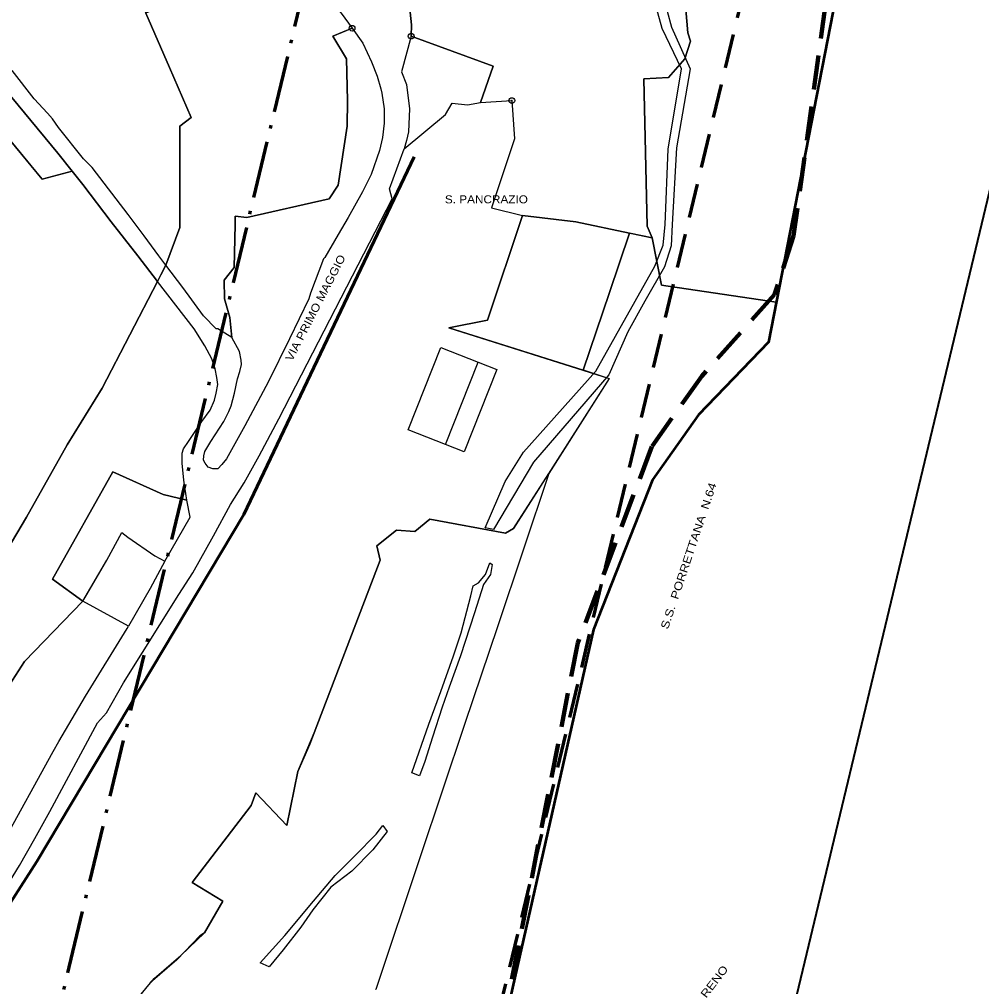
# Model space of a CAD drawing. Extents: x 654952 to 658955, y 890426 to 894481.
# Drawn here: x 657975.8 to 658312.8, y 892673.6 to 893012.3 of the extents above; entities that cross this region are included whole.
import ezdxf

# ---------------------------------------------------------------- set-up
doc = ezdxf.new("R2010")
doc.units = 0
doc.header["$LTSCALE"] = 4
doc.header["$PDMODE"] = 32
doc.header["$PDSIZE"] = 2
doc.linetypes.add('DOT_DASHED', pattern=[7.7, 5, -1.2, 0.3, -1.2])
doc.linetypes.add('MEDIUM_DASHED', pattern=[4.5, 3, -1.5])
for name, color, linetype, lineweight in [('1', 7, 'Continuous', 25), ('14', 7, 'Continuous', 25), ('18', 7, 'Continuous', 25), ('20', 7, 'Continuous', 25), ('29', 7, 'Continuous', 25), ('40', 7, 'Continuous', 60), ('43', 7, 'Continuous', 25), ('45', 7, 'Continuous', 25), ('5', 7, 'Continuous', 25), ('55', 7, 'Continuous', 25), ('57', 7, 'Continuous', 25), ('59', 7, 'Continuous', 53), ('6', 7, 'Continuous', 25), ('7', 7, 'MEDIUM_DASHED', 100), ('9', 7, 'Continuous', 25)]:
    doc.layers.add(name, color=color, linetype=linetype, lineweight=lineweight)
doc.layers.add('58', color=7, linetype='Continuous')

msp = doc.modelspace()

# ---------------------------------------------------------------- linework, layer by layer
at = {"layer": '1'}
for points in [[(657998.02, 892808.54), (657999.47, 892810.89), (658006.47, 892822.89), (658011.7, 892832.58), (658013.75, 892830.94), (658023.25, 892824.44)], [(658023.25, 892824.44), (658026.8, 892822.52), (658021.63, 892812.94), (658013.98, 892799.82), (657998.08, 892808.51)]]:
    msp.add_lwpolyline(points, dxfattribs=at)
at = {"layer": '14'}
for points in [[(658077.75, 892916.44), (658077.13, 892914.44), (658070.37, 892900.44), (658063, 892885.44), (658054.75, 892869.94), (658048.37, 892858.44), (658046.75, 892856.44), (658045.25, 892854.94), (658043.5, 892854.94), (658041.87, 892855.44), (658040.87, 892856.94), (658040.25, 892857.94), (658040.37, 892859.44), (658040.75, 892860.94), (658042.87, 892864.44), (658047.38, 892871.44), (658049.13, 892874.94), (658050, 892876.94), (658051.13, 892881.44), (658052.25, 892886.44), (658053, 892888.94), (658053.63, 892891.44), (658053.5, 892892.94), (658052.87, 892895.94), (658050.25, 892900.94), (658049.5, 892907.94), (658047.63, 892914.44), (658047.5, 892920.94), (658051.06, 892925.44), (658051.37, 892940.44), (658051.37, 892943.44), (658055.5, 892942.94), (658084.25, 892949.44), (658087.44, 892954.19), (658090.63, 892974.94), (658090.75, 892983.94), (658090.31, 892998.44), (658085.63, 893006.44), (658092.31, 893009.19)], [(658092.31, 893009.19), (658092.31, 893009.19), (658096.13, 893003.94), (658099.13, 892997.44), (658101.13, 892992.44), (658102.37, 892987.94), (658102.75, 892986.44)], [(658102.75, 892986.44), (658103.5, 892980.94), (658103.5, 892975.94), (658103, 892970.94), (658101.87, 892966.44), (658099, 892957.94), (658096, 892951.94), (658091, 892942.94), (658087.5, 892936.94), (658082.75, 892928.94), (658082.25, 892928.44), (658077.75, 892916.44)]]:
    msp.add_lwpolyline(points, dxfattribs=at)
msp.add_point((658092.31, 893009.19), dxfattribs=at)
at = {"layer": '18'}
for points in [[(657994.29, 892959.11), (657989.25, 892965.44), (657968.05, 892991.04), (657966.89, 892992.59), (657957.1, 892988.98), (657960.05, 892985.04), (657960.35, 892984.66)], [(657960.35, 892984.66), (657981.49, 892959.14), (657983.75, 892956.29), (657994.29, 892959.11)]]:
    msp.add_lwpolyline(points, dxfattribs=at)
at = {"layer": '20'}
msp.add_line((658026.13, 892845.94), (658034.45, 892843.92), dxfattribs=at)
for points in [[(658024.17, 892920.51), (658017.25, 892929.44), (658008, 892941.44), (657998, 892954.44), (657994.29, 892959.11), (657983.75, 892956.29), (657967.25, 892976.32), (657932.13, 892896.94), (657930.01, 892892.15), (657906.64, 892839.36), (657926, 892830.44), (657930.13, 892846.94), (657960.5, 892838.94), (657961.09, 892814.26), (657961.21, 892809.33)], [(658024.17, 892920.51), (658004.83, 892883.1), (657992.56, 892863.36), (657978.36, 892837.99), (657961.21, 892809.33), (657961.5, 892797.44), (657962.87, 892782.94), (657962.48, 892768.22), (657964.75, 892767.48), (657969.21, 892774.37), (657977.66, 892787.42), (657998.02, 892808.54)], [(657961.21, 892809.33), (657978.36, 892837.99), (657992.56, 892863.36), (658004.83, 892883.1), (658024.17, 892920.51)], [(658034.45, 892843.92), (658033.37, 892850.94), (658032.87, 892856.94), (658032.87, 892860.44), (658033.25, 892861.94), (658035, 892864.44), (658039.75, 892871.44), (658042.63, 892875.44), (658044.13, 892878.94), (658044.75, 892881.44), (658045.25, 892884.44), (658045, 892886.94), (658044.37, 892889.94), (658043.25, 892893.44), (658040.75, 892897.94), (658037, 892903.94), (658024.17, 892920.51)], [(657998.02, 892808.54), (657987.36, 892816.2), (658008.58, 892853.84), (658026.13, 892845.94)]]:
    msp.add_lwpolyline(points, dxfattribs=at)
at = {"layer": '29'}
for points in [[(658222.69, 893076.77), (658218.01, 893077.46), (658207.53, 893075.52), (658196.6, 893076.12), (658185.51, 893078.96), (658169.41, 893074.9), (658169.53, 893074.45), (658153.5, 893069.94), (658152, 893062.44), (658144.5, 893060.94), (658133.63, 893069.44), (658129.75, 893066.44), (658108.5, 893069.94), (658106.87, 893067.94), (658106.75, 893058.44), (658107.75, 893046.94), (658109.25, 893046.94), (658113.13, 893010.44), (658113, 893006.44)], [(658203.13, 892991.94), (658208.87, 892998.44), (658210.87, 893004.69), (658209.9, 893007.55), (658208.52, 893024.05), (658215.39, 893024.69), (658218.4, 893043.42), (658221.75, 893066.94), (658222.69, 893076.77)], [(658113, 893006.44), (658141.75, 892995.94), (658137.25, 892983.17), (658148.26, 892983.85)], [(658195.63, 892939.94), (658194.44, 892991.44), (658203.13, 892991.94)], [(658106.37, 892949.44), (658105.37, 892952.94), (658110.5, 892966.94), (658125, 892978.94), (658127.37, 892982.94), (658132.74, 892982.34), (658137.25, 892983.17), (658148.26, 892983.85), (658149.18, 892970.5), (658141.15, 892946.27), (658151.94, 892943.62)], [(658148.26, 892983.85), (658149.18, 892970.5), (658141.15, 892946.27), (658151.94, 892943.62), (658170.62, 892941.41)], [(657975.87, 892715.94), (657981.19, 892725.44), (657986.5, 892734.94), (658003.13, 892765.94), (658006.37, 892769.44), (658012.25, 892779.94), (658031.63, 892810.94), (658036.5, 892818.44), (658043.75, 892831.44), (658049.75, 892842.44), (658054.5, 892849.94), (658059.81, 892859.44), (658066.63, 892872.44), (658106.37, 892949.44)], [(658151.94, 892943.62), (658139.73, 892906.94), (658126.18, 892904.28)], [(658170.62, 892941.41), (658197.42, 892935.77), (658195.63, 892939.94)], [(658126.18, 892904.28), (658182.31, 892886.53), (658148.87, 892834.03), (658146, 892832.35), (658119.5, 892837.28), (658114.24, 892832.91), (658107.87, 892833.47), (658101, 892827.94), (658102.13, 892822.94), (658077.5, 892758.44), (658073.37, 892748.94), (658069.5, 892729.94), (658058.63, 892741.44), (658057, 892736.94), (658036.31, 892709.98), (658047, 892703.44), (658040.63, 892692.44), (658038.98, 892691.29)], [(657956, 892639.44), (657953.37, 892639.94), (657950.75, 892640.94), (657948.5, 892641.94), (657945.87, 892644.44), (657937.08, 892655.43), (657938.63, 892657.44), (657944.5, 892665.94), (657950.75, 892674.44), (657956.5, 892680.94), (657965.13, 892698.44), (657970.5, 892707.19), (657975.87, 892715.94)], [(658038.98, 892691.29), (658031, 892682.94), (658021.63, 892674.94), (658011.87, 892663.07), (658000.87, 892634.44)]]:
    msp.add_lwpolyline(points, dxfattribs=at)
for p in [(658113, 893006.44), (658148.26, 892983.85)]:
    msp.add_point(p, dxfattribs=at)
at = {"layer": '40'}
msp.add_lwpolyline([(658114.09, 892964.13), (658054.45, 892838.86), (657981.91, 892717.36), (657940.54, 892652.83)], dxfattribs=at)
at = {"layer": '43'}
for points in [[(658194.44, 892991.44), (658195.63, 892939.94), (658197.42, 892935.77), (658200.61, 892919.2), (658240.85, 892913.21), (658275.65, 893091.39), (658324.67, 893198.8), (658324.98, 893205.94), (658316.81, 893217.01), (658315.67, 893225.5), (658324.05, 893218.98), (658327.46, 893312.74), (658329.63, 893434.42)], [(658268.57, 893152.66), (658268.57, 893152.66), (658267.64, 893148.16), (658262.84, 893094.33), (658259.82, 893073.82), (658233.93, 893075.3), (658222.69, 893076.77), (658221.75, 893066.94), (658218.4, 893043.42), (658215.39, 893024.69), (658208.52, 893024.05), (658209.9, 893007.55), (658210.87, 893004.69), (658208.87, 892998.44), (658203.13, 892991.94), (658194.44, 892991.44)], [(658126.18, 892904.28), (658139.73, 892906.94), (658151.94, 892943.62), (658170.62, 892941.41), (658189.43, 892937.45)], [(658189.43, 892937.45), (658182.4, 892916.68), (658173.22, 892889.4), (658126.18, 892904.28)], [(658240.85, 892913.21), (658200.61, 892919.2), (658197.42, 892935.77), (658189.43, 892937.45), (658182.4, 892916.68), (658173.29, 892889.6)], [(658040.09, 892492.62), (658056.01, 892512.42), (658077.73, 892541.6), (658117.44, 892608.97), (658146.29, 892663.3), (658176.86, 892798.67), (658197.47, 892851.1), (658213.6, 892873.76), (658238.11, 892899.22), (658240.85, 892913.21)], [(658173.29, 892889.6), (658182.31, 892886.53), (658161.16, 892853.31), (658143.25, 892799.61), (658131.77, 892765.67), (658116.11, 892719.06), (658100.59, 892672.5), (658100.64, 892672.66)], [(657983.56, 892634.54), (657998.75, 892631.44), (658000.87, 892634.44), (658011.87, 892663.07), (658023.01, 892676.46), (658032.38, 892684.45), (658040.63, 892692.44), (658047, 892703.44), (658036.31, 892709.98), (658057, 892736.94), (658058.63, 892741.44), (658069.5, 892729.94), (658073.37, 892748.94), (658079, 892762.39), (658102.13, 892822.94), (658101, 892827.94), (658107.87, 892833.47), (658114.24, 892832.91), (658119.5, 892837.28), (658146, 892832.35), (658148.87, 892834.03), (658161.16, 892853.31)], [(658161.16, 892853.31), (658143.25, 892799.61), (658131.77, 892765.67), (658116.11, 892719.06), (658100.59, 892672.5), (658100.64, 892672.66)]]:
    msp.add_lwpolyline(points, dxfattribs=at)
msp.add_lwpolyline([(658173.22, 892889.4), (658182.4, 892916.68), (658189.43, 892937.45), (658170.62, 892941.41), (658151.94, 892943.62), (658139.73, 892906.94), (658126.18, 892904.28)], close=True, dxfattribs=at)
at = {"layer": '45', "linetype": 'DOT_DASHED', "lineweight": 70}
msp.add_lwpolyline([(657888.75, 892244.36), (657949.53, 892498.78), (657993.28, 892680.38), (658112.95, 893179.41), (658123.49, 893235.71), (658127.84, 893290.79), (658125.12, 893359.25), (658122.7, 893382.9), (658114.35, 893470.93), (658113.32, 893505.97), (658113.89, 893537.78), (658115.35, 893563.44), (658117.94, 893594.58), (658121.29, 893618.7), (658125.97, 893646.13), (658131.56, 893672.78), (658136.29, 893692.48), (658143.9, 893719.95), (658153.86, 893751.08), (658170.87, 893795.19), (658185.72, 893828.64), (658194.88, 893846.97), (658209.57, 893874.93), (658233.56, 893914.96)], dxfattribs=at)
at = {"layer": '45', "linetype": 'MEDIUM_DASHED', "lineweight": 70}
msp.add_lwpolyline([(658035.6, 892213.52), (658095.39, 892463.77), (658139.14, 892645.31), (658259.68, 893148.09), (658272.39, 893215.94), (658278.08, 893287.85), (658274.82, 893369.87), (658271.98, 893397.63), (658264.14, 893480.23), (658263.35, 893506.84), (658263.8, 893532.17), (658264.99, 893552.95), (658267.07, 893578), (658269.55, 893595.75), (658273.36, 893618.11), (658277.93, 893639.87), (658281.55, 893654.95), (658287.66, 893677.05), (658295.4, 893701.19), (658309.47, 893737.74), (658321.42, 893764.63), (658328.38, 893778.55), (658340.4, 893801.43), (658362.23, 893837.86)], dxfattribs=at)
at = {"layer": '45', "lineweight": 40}
msp.add_lwpolyline([(658133.5, 892192.94), (658192.63, 892440.44), (658236.37, 892621.94), (658357.51, 893127.22), (658371.66, 893202.76), (658378.23, 893285.88), (658374.62, 893376.94), (658371.5, 893407.44), (658364, 893486.44), (658363.38, 893507.44), (658363.75, 893528.44), (658364.75, 893545.94), (658366.5, 893566.94), (658368.38, 893580.44), (658371.62, 893599.44), (658375.5, 893617.94), (658378.38, 893629.94), (658383.5, 893648.44), (658389.75, 893667.94), (658401.88, 893699.44), (658411.88, 893721.94), (658417.38, 893732.94), (658427.62, 893752.44), (658448, 893786.44)], dxfattribs=at)
at = {"layer": '5'}
for points in [[(657994.29, 892959.11), (657998, 892954.44), (658008, 892941.44), (658017.25, 892929.44), (658024.17, 892920.51), (658027.1, 892926.19), (658024.63, 892929.44), (658019.5, 892936.44), (658013.87, 892943.94), (658005.5, 892954.94), (658001.25, 892960.44), (657998.25, 892963.44), (657989.5, 892974.44), (657987.37, 892977.44), (657985.63, 892979.44), (657981, 892984.44), (657973.25, 892994.44)], [(657968.05, 892991.04), (657989.25, 892965.44), (657994.29, 892959.11)]]:
    msp.add_lwpolyline(points, dxfattribs=at)
at = {"layer": '55'}
for points in [[(658040.09, 892492.62), (658056.01, 892512.42), (658077.73, 892541.6), (658117.44, 892608.97), (658146.29, 892663.3), (658176.86, 892798.67), (658197.47, 892851.1), (658213.6, 892873.76), (658238.11, 892899.22), (658275.65, 893091.38), (658324.67, 893198.8), (658324.98, 893205.94), (658316.81, 893217.01), (658315.67, 893225.5), (658324.05, 893218.98), (658327.46, 893312.74), (658329.63, 893434.42), (658329.32, 893488.12), (658323.74, 893553.3), (658322.5, 893619.12), (658343.9, 893727.46), (658358.49, 893763.16), (658400.68, 893840.75), (658381.79, 893852.16)], [(657993.13, 893069.94), (658008.63, 893070.94), (658019.5, 893050.94), (658023.87, 893052.44), (658031.5, 893043.44), (658030.13, 893041.94), (658042.8, 893024.46), (658020.13, 893014.44), (658028.37, 892995.44), (658036, 892977.94), (658032, 892974.94), (658032, 892939.44), (658027.1, 892926.19), (658004.83, 892883.1), (657992.56, 892863.36), (657978.36, 892837.99), (657946.04, 892783.96)], [(658113, 893006.44), (658113.13, 893010.44), (658109.25, 893046.94), (658107.75, 893046.94), (658106.75, 893058.44), (658106.87, 893067.94), (658108.5, 893069.94), (658114.73, 893068.91)], [(658215.39, 893024.69), (658208.52, 893024.05), (658209.9, 893007.55), (658210.87, 893004.69), (658208.87, 892998.44), (658203.13, 892991.94), (658194.44, 892991.44), (658195.29, 892954.75)], [(658106.37, 892949.44), (658105.37, 892952.94), (658110.5, 892966.94), (658125, 892978.94), (658127.37, 892982.94), (658132.74, 892982.34), (658137.25, 892983.17), (658141.75, 892995.94), (658113, 893006.44)], [(658195.29, 892954.75), (658195.63, 892939.94), (658197.42, 892935.77), (658189.43, 892937.45), (658182.4, 892916.68), (658173.29, 892889.6), (658182.31, 892886.53), (658161.16, 892853.31), (658143.25, 892799.61), (658131.77, 892765.67), (658116.11, 892719.06), (658100.59, 892672.5), (658100.64, 892672.66)], [(657944.5, 892665.94), (657950.75, 892674.44), (657956.5, 892680.94), (657965.13, 892698.44), (657970.5, 892707.19), (657975.87, 892715.94), (657981.19, 892725.44), (657986.5, 892734.94), (658003.13, 892765.94), (658006.37, 892769.44), (658012.25, 892779.94), (658031.63, 892810.94), (658036.5, 892818.44), (658043.75, 892831.44), (658049.75, 892842.44), (658054.5, 892849.94), (658059.81, 892859.44), (658066.63, 892872.44), (658106.37, 892949.44)]]:
    msp.add_lwpolyline(points, dxfattribs=at)
msp.add_point((658113, 893006.44), dxfattribs=at)
at = {"layer": '57'}
for points in [[(658138.93, 892834.25), (658145.93, 892850.5), (658152.37, 892860.75), (658177.62, 892889.06), (658198.37, 892925.87), (658201.24, 892933.19), (658201.99, 892940.5), (658202.99, 892966.81), (658207.68, 892995), (658200.93, 893009.06), (658190.05, 893048.37), (658183.31, 893070.44), (658183.43, 893082.94), (658183.31, 893088.5), (658182.62, 893095.44), (658174.12, 893126.94), (658170.99, 893149.94), (658173.93, 893167.87), (658177.87, 893167.44)], [(658177.87, 893167.44), (658174.31, 893149.44), (658176.43, 893133.75), (658177.37, 893129.63), (658186.31, 893095.13), (658187.24, 893083.44), (658187.18, 893083.19), (658186.18, 893071.13), (658193.49, 893048.94), (658204.12, 893009.56), (658210.74, 892994.94), (658205.87, 892967.31), (658204.43, 892940.44), (658204.05, 892932.94), (658201.74, 892925.63), (658194.81, 892913.63), (658188.93, 892902.87), (658182.18, 892887.87), (658155.81, 892857.19), (658141.87, 892833.69), (658138.93, 892834.25)]]:
    msp.add_lwpolyline(points, dxfattribs=at)
for points in [[(658113.25, 892748.44), (658119.25, 892765.44), (658123.37, 892776.94), (658127.87, 892789.44), (658130.5, 892797.44), (658133.87, 892810.44), (658134.75, 892813.94), (658136.63, 892814.94), (658139, 892817.94), (658140.5, 892821.94), (658141.37, 892821.44), (658140.75, 892817.94), (658138.37, 892814.44), (658135.13, 892804.44), (658130.25, 892789.44), (658126.37, 892778.44), (658123.87, 892771.44), (658120.5, 892760.94), (658117.75, 892752.44), (658115.87, 892747.44)], [(658060.13, 892681.94), (658068.75, 892691.44), (658078.75, 892703.44), (658086.37, 892712.44), (658093.37, 892719.44), (658100.75, 892726.94), (658103.13, 892729.94), (658104.63, 892727.94), (658099.63, 892721.44), (658092.25, 892713.94), (658084.87, 892708.44), (658078.63, 892700.44), (658074.37, 892694.44), (658068.13, 892686.44), (658063.25, 892680.44)]]:
    msp.add_lwpolyline(points, close=True, dxfattribs=at)
at = {"layer": '59'}
msp.add_lwpolyline([(658343.9, 893727.46), (658322.5, 893619.12), (658323.74, 893553.3), (658329.32, 893488.12), (658329.63, 893434.42), (658327.46, 893312.74), (658324.05, 893218.98), (658315.67, 893225.5), (658316.81, 893217.01), (658324.98, 893205.94), (658324.67, 893198.8), (658275.65, 893091.38), (658238.11, 892899.22), (658213.6, 892873.76), (658197.47, 892851.1), (658176.86, 892798.67), (658146.29, 892663.3), (658117.44, 892608.97), (658077.73, 892541.6), (658056.01, 892512.42), (658015.06, 892461.51), (657983.11, 892330.2)], dxfattribs=at)
at = {"layer": '6'}
msp.add_line((658125.03, 892863.4), (658136.44, 892892.23), dxfattribs=at)
msp.add_lwpolyline([(658112.01, 892868.55), (658123.42, 892897.38), (658142.95, 892889.65), (658131.54, 892860.83)], close=True, dxfattribs=at)
at = {"layer": '7'}
msp.add_lwpolyline([(658345.21, 893730.15), (658324.56, 893626.35), (658326.18, 893565.54), (658329.82, 893531.88), (658330.62, 893468.63), (658337.11, 893409.83), (658336.7, 893350.23), (658336.29, 893306.44), (658326.56, 893216.03), (658269.02, 893100.07), (658258.05, 893017.47), (658246.92, 892936.53), (658240.25, 892915.99), (658214.74, 892887.33), (658197.25, 892862.68), (658171.38, 892793.94), (658146.27, 892665.82), (658107.77, 892604.19), (658053.07, 892513.78), (658011.87, 892462.81), (657985.13, 892331.98)], dxfattribs=at)
at = {"layer": '9'}
for points in [[(657964, 893044.94), (657978.35, 893022.67), (657988, 893025.94), (657995.75, 893028.44), (658011.5, 893033.94), (658020.13, 893014.44), (658028.37, 892995.44), (658036, 892977.94), (658032, 892974.94), (658032, 892939.44), (658027.1, 892926.19), (658024.63, 892929.44), (658019.5, 892936.44), (658013.87, 892943.94), (658005.5, 892954.94), (658001.25, 892960.44), (657998.25, 892963.44), (657989.5, 892974.44), (657987.37, 892977.44), (657985.63, 892979.44), (657981, 892984.44), (657973.25, 892994.44)], [(658085.5, 893017.94), (658088.5, 893014.44), (658092.31, 893009.19), (658092.31, 893009.19), (658092.31, 893009.19), (658092.31, 893009.19)], [(658045.25, 892903.94), (658044.75, 892903.94), (658040.25, 892908.44), (658033, 892918.44), (658027.1, 892926.19), (658032, 892939.44), (658032, 892974.94), (658036, 892977.94), (658028.37, 892995.44), (658020.13, 893014.44)], [(658092.31, 893009.19), (658085.63, 893006.44), (658090.31, 892998.44), (658090.75, 892983.94), (658090.63, 892974.94), (658087.44, 892954.19), (658084.25, 892949.44), (658055.5, 892942.94), (658051.37, 892943.44), (658051.37, 892940.44), (658051.06, 892925.44), (658047.5, 892920.94), (658047.63, 892914.44), (658049.5, 892907.94), (658050.25, 892900.94), (658045.25, 892903.94)], [(658008.58, 892853.84), (657987.36, 892816.2), (657998.02, 892808.54), (658006.47, 892822.89), (658011.7, 892832.58), (658013.75, 892830.94)], [(658034.45, 892843.92), (658026.13, 892845.94), (658008.58, 892853.84)], [(658013.75, 892830.94), (658023.25, 892824.44), (658026.8, 892822.52), (658035.63, 892837.94), (658034.45, 892843.92)], [(657998.02, 892808.54), (657977.66, 892787.42), (657969.21, 892774.37), (657964.75, 892767.48), (657962.48, 892768.22), (657958.61, 892769.49), (657957.13, 892764.94), (657954.75, 892758.44), (657953.25, 892754.44), (657950.13, 892749.44), (657948.63, 892745.44), (657947.87, 892740.94), (657946.37, 892737.94), (657936.75, 892719.94), (657938, 892712.94), (657953.25, 892706.44), (657959.63, 892702.94)], [(657959.63, 892702.94), (657966.13, 892714.94), (657969.75, 892723.44), (657987.63, 892755.94), (657989.63, 892759.44), (657998.98, 892775.24), (658013.51, 892799.02), (658013.98, 892799.82), (657998.08, 892808.51), (657998.02, 892808.54)]]:
    msp.add_lwpolyline(points, dxfattribs=at)
msp.add_lwpolyline([(658113, 893006.44), (658109.63, 892993.94), (658111.37, 892989.44), (658112.37, 892980.94), (658112.13, 892972.94), (658111.32, 892969.94), (658110.5, 892966.94), (658125, 892978.94), (658127.37, 892982.94), (658132.74, 892982.34), (658137.25, 892983.17), (658141.75, 892995.94)], close=True, dxfattribs=at)
msp.add_point((658092.31, 893009.19), dxfattribs=at)

# ---------------------------------------------------------------- texts
at = {"layer": '58', "width": 1.1}
msp.add_text('S. PANCRAZIO', height=2.801, dxfattribs=at).set_placement((658124.81, 892947.88))
at = {"layer": '58'}
for s, height, rotation, width, p in [('VIA PRIMO MAGGIO', 2.802, 62.792, 1.15, (658071.32, 892892.35)), ('S.S.  PORRETTANA  N.64', 2.802, 71.464, 1.2, (658202.93, 892798.52)), ('RENO', 2.797, 52.49, 1.2, (658216.33, 892669.34))]:
    msp.add_text(s, height=height, rotation=rotation, dxfattribs=dict(at, width=width)).set_placement(p)

doc.saveas('drawing.dxf')
